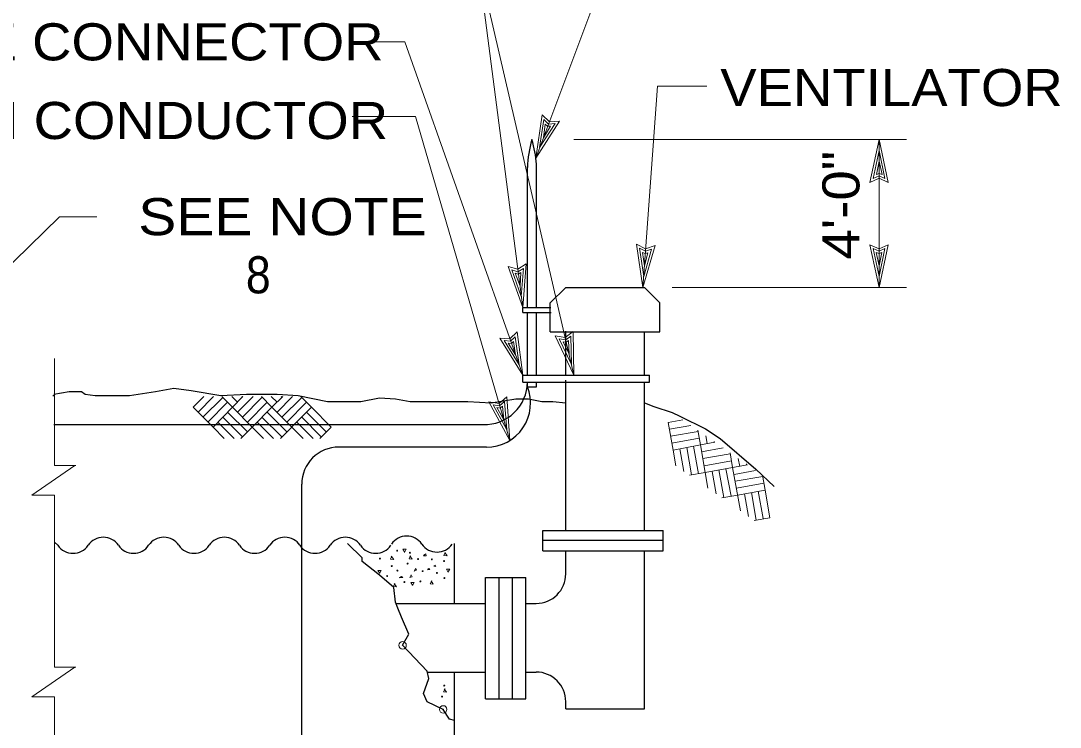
# Model space of a CAD drawing. Extents: x -39.6 to 16.1, y -17.6 to 34.
# Drawn here: x -5.055 to -1.551, y 7.321 to 9.702 of the extents above; entities that cross this region are included whole.
import ezdxf
from ezdxf.enums import TextEntityAlignment as Align

# ---------------------------------------------------------------- set-up
doc = ezdxf.new("R2010")
doc.units = 0
doc.header["$LTSCALE"] = 0.05
doc.header["$PDMODE"] = 32
doc.header["$PDSIZE"] = 0.025
doc.layers.add('1', color=7, linetype='Continuous', lineweight=13)
doc.layers.add('2', color=7, linetype='Continuous', lineweight=13)

msp = doc.modelspace()

# ---------------------------------------------------------------- linework, layer by layer
at = {"layer": '1'}
for p, q in [((-3.11621, 9.77942), (-3.31921, 9.23942)), ((-2.90921, 9.48142), (-2.74321, 9.48142)), ((-3.31921, 9.23942), (-3.29721, 9.38542)), ((-3.31921, 9.23942), (-3.23921, 9.36342)), ((-3.30621, 9.27442), (-3.29221, 9.36942)), ((-3.30621, 9.27442), (-3.25421, 9.35542)), ((-3.29221, 9.36942), (-3.27621, 9.35342)), ((-3.27621, 9.35342), (-3.25421, 9.35542)), ((-3.29321, 9.30742), (-3.28721, 9.35342)), ((-3.29321, 9.30742), (-3.26921, 9.34642)), ((-3.28721, 9.35342), (-3.27921, 9.34642)), ((-3.27921, 9.34642), (-3.26921, 9.34642)), ((-3.19121, 9.30142), (-2.06921, 9.30142)), ((-2.16221, 9.30142), (-2.19321, 9.15742)), ((-2.16221, 8.80342), (-2.16221, 9.30142)), ((-2.16221, 9.30142), (-2.13121, 9.15742)), ((-2.16221, 9.26442), (-2.18221, 9.17042)), ((-2.16221, 9.26442), (-2.14221, 9.17042)), ((-2.16221, 9.22842), (-2.17121, 9.18342)), ((-2.16221, 9.22842), (-2.15221, 9.18342)), ((-2.16221, 9.18742), (-2.17121, 9.18342)), ((-2.15221, 9.18342), (-2.16221, 9.18742)), ((-2.16221, 9.17942), (-2.18221, 9.17042)), ((-2.14221, 9.17042), (-2.16221, 9.17942)), ((-4.92421, 9.04142), (-4.79921, 9.04142)), ((-2.95521, 8.84042), (-2.96921, 8.93542)), ((-2.96921, 8.93542), (-2.94921, 8.92542)), ((-2.95821, 8.80342), (-2.91721, 8.94442)), ((-2.16221, 8.80342), (-2.19321, 8.94742)), ((-2.16221, 8.80342), (-2.13121, 8.94742)), ((-2.95321, 8.87642), (-2.95921, 8.92142)), ((-2.95921, 8.92142), (-2.95021, 8.91742)), ((-2.95521, 8.84042), (-2.92921, 8.93242)), ((-2.95321, 8.87642), (-2.94121, 8.92042)), ((-2.95021, 8.91742), (-2.94121, 8.92042)), ((-2.94921, 8.92542), (-2.92921, 8.93242)), ((-2.16221, 8.84042), (-2.18221, 8.93442)), ((-2.18221, 8.93442), (-2.16221, 8.92542)), ((-2.16221, 8.87642), (-2.17221, 8.92142)), ((-2.17221, 8.92142), (-2.16221, 8.91742)), ((-2.16221, 8.84042), (-2.14221, 8.93442)), ((-2.16221, 8.92542), (-2.14221, 8.93442)), ((-2.16221, 8.87642), (-2.15321, 8.92142)), ((-2.16221, 8.91742), (-2.15321, 8.92142)), ((-3.37921, 8.85642), (-3.36021, 8.86742)), ((-3.36821, 8.77242), (-3.36021, 8.86742)), ((-3.36321, 8.73542), (-3.35121, 8.88242)), ((-3.36821, 8.77242), (-3.40021, 8.86242)), ((-3.40021, 8.86242), (-3.37921, 8.85642)), ((-3.37221, 8.80742), (-3.38821, 8.85142)), ((-3.38821, 8.85142), (-3.37821, 8.84842)), ((-3.37821, 8.84842), (-3.36921, 8.85342)), ((-3.37221, 8.80742), (-3.36921, 8.85342)), ((-2.85921, 8.80342), (-2.06921, 8.80342)), ((-3.19121, 8.50742), (-3.19321, 8.65442)), ((-3.37521, 8.54242), (-3.42621, 8.62442)), ((-3.42621, 8.62442), (-3.40421, 8.62242)), ((-3.40421, 8.62242), (-3.38821, 8.63742)), ((-3.40121, 8.61442), (-3.39421, 8.62142)), ((-3.38721, 8.57642), (-3.39421, 8.62142)), ((-3.37521, 8.54242), (-3.38821, 8.63742)), ((-3.36321, 8.50742), (-3.38221, 8.65342)), ((-3.19121, 8.50742), (-3.25421, 8.64042)), ((-3.19921, 8.54342), (-3.24021, 8.63042)), ((-3.24021, 8.63042), (-3.21821, 8.62642)), ((-3.20721, 8.57842), (-3.22721, 8.62042)), ((-3.22721, 8.62042), (-3.21721, 8.61842)), ((-3.21821, 8.62642), (-3.20121, 8.63942)), ((-3.21721, 8.61842), (-3.20921, 8.62442)), ((-3.20721, 8.57842), (-3.20921, 8.62442)), ((-3.19921, 8.54342), (-3.20121, 8.63942)), ((-3.38721, 8.57642), (-3.41221, 8.61542)), ((-3.41221, 8.61542), (-3.40121, 8.61442)), ((-4.94121, 8.20342), (-4.94121, 8.56342)), ((-4.47421, 8.39942), (-4.43821, 8.43542)), ((-4.45721, 8.38342), (-4.40521, 8.43542)), ((-4.44121, 8.36642), (-4.37421, 8.43242)), ((-4.42421, 8.34942), (-4.35821, 8.41642)), ((-4.34121, 8.39942), (-4.37721, 8.43542)), ((-4.32521, 8.41642), (-4.34421, 8.43542)), ((-4.34121, 8.39942), (-4.30621, 8.43542)), ((-4.34121, 8.39942), (-4.30621, 8.43542)), ((-4.32521, 8.38342), (-4.27221, 8.43542)), ((-4.30821, 8.43242), (-4.31021, 8.43542)), ((-4.30821, 8.36642), (-4.24221, 8.43242)), ((-4.29121, 8.34942), (-4.22521, 8.41642)), ((-4.20921, 8.39942), (-4.24421, 8.43542)), ((-4.19121, 8.41642), (-4.21121, 8.43542)), ((-4.20921, 8.39942), (-4.17221, 8.43542)), ((-4.19121, 8.38342), (-4.13921, 8.43542)), ((-4.17521, 8.43242), (-4.17721, 8.43542)), ((-4.17521, 8.36642), (-4.10821, 8.43242)), ((-4.15821, 8.34942), (-4.09221, 8.41642)), ((-4.07521, 8.39942), (-4.11121, 8.43542)), ((-3.44121, 8.40442), (-3.42421, 8.41842)), ((-3.41721, 8.32342), (-3.42421, 8.41842)), ((-3.40721, 8.28742), (-3.41721, 8.43442)), ((-4.40721, 8.33242), (-4.34121, 8.39942)), ((-4.29121, 8.31642), (-4.35821, 8.38342)), ((-4.27521, 8.33242), (-4.34121, 8.39942)), ((-4.27521, 8.33242), (-4.20921, 8.39942)), ((-4.15821, 8.31642), (-4.22521, 8.38342)), ((-4.14221, 8.33242), (-4.07521, 8.39942)), ((-4.02621, 8.31642), (-4.09221, 8.38342)), ((-4.00921, 8.33242), (-4.07521, 8.39942)), ((-3.41721, 8.32342), (-3.46321, 8.40742)), ((-3.46321, 8.40742), (-3.44121, 8.40442)), ((-3.42721, 8.35742), (-3.45021, 8.39842)), ((-3.45021, 8.39842), (-3.43921, 8.39642)), ((-3.43921, 8.39642), (-3.43121, 8.40342)), ((-3.42721, 8.35742), (-3.43121, 8.40342)), ((-4.33621, 8.29442), (-4.39121, 8.34942)), ((-4.30821, 8.29942), (-4.37421, 8.36642)), ((-4.20321, 8.29442), (-4.25821, 8.34942)), ((-4.17521, 8.29942), (-4.24221, 8.36642)), ((-4.07021, 8.29442), (-4.12521, 8.34942)), ((-4.04221, 8.29942), (-4.10821, 8.36642)), ((-2.87321, 8.34842), (-2.82321, 8.35742)), ((-4.31321, 8.29442), (-4.27521, 8.33242)), ((-4.23721, 8.29442), (-4.27521, 8.33242)), ((-4.18021, 8.29442), (-4.14121, 8.33242)), ((-4.04721, 8.29442), (-4.00921, 8.33242)), ((-2.86821, 8.32542), (-2.79621, 8.33842)), ((-2.86521, 8.30242), (-2.77221, 8.31842)), ((-2.76421, 8.27242), (-2.77321, 8.32242)), ((-2.86121, 8.27842), (-2.76821, 8.29542)), ((-2.85621, 8.25442), (-2.76421, 8.27242)), ((-2.76421, 8.27242), (-2.71521, 8.28142)), ((-2.76421, 8.27242), (-2.71521, 8.28142)), ((-2.74821, 8.17942), (-2.76421, 8.27242)), ((-2.74121, 8.27742), (-2.74621, 8.30342)), ((-2.71821, 8.28042), (-2.71821, 8.28442)), ((-2.82021, 8.18342), (-2.83421, 8.25942)), ((-2.79421, 8.17142), (-2.81021, 8.26342)), ((-2.77021, 8.17542), (-2.78721, 8.26842)), ((-2.76021, 8.24942), (-2.68721, 8.26242)), ((-2.75621, 8.22642), (-2.66421, 8.24242)), ((-2.65621, 8.19642), (-2.66421, 8.24642)), ((-5.01821, 8.10342), (-4.87321, 8.20342)), ((-4.94121, 8.20342), (-4.86921, 8.20342)), ((-2.75221, 8.20242), (-2.65921, 8.21942)), ((-2.65621, 8.19642), (-2.60521, 8.20542)), ((-2.63121, 8.20042), (-2.63721, 8.22742)), ((-2.60921, 8.20442), (-2.60921, 8.20842)), ((-2.80121, 8.17042), (-2.74821, 8.17942)), ((-2.74821, 8.17942), (-2.65621, 8.19642)), ((-2.73921, 8.12642), (-2.74821, 8.17942)), ((-2.71121, 8.10742), (-2.72421, 8.18342)), ((-2.68521, 8.09542), (-2.70221, 8.18842)), ((-2.66121, 8.09942), (-2.67821, 8.19242)), ((-2.65021, 8.17342), (-2.57821, 8.18642)), ((-2.64721, 8.15042), (-2.55421, 8.16642)), ((-2.54621, 8.12042), (-2.55521, 8.17042)), ((-2.64221, 8.12642), (-2.55021, 8.14342)), ((-5.01821, 8.10342), (-4.94121, 8.10342)), ((-4.94121, 7.52342), (-4.94121, 8.10342)), ((-2.69221, 8.09442), (-2.63821, 8.10342)), ((-2.63921, 8.10342), (-2.54621, 8.12042)), ((-2.60221, 8.03142), (-2.61521, 8.10742)), ((-2.57621, 8.01942), (-2.59221, 8.11242)), ((-2.55321, 8.02442), (-2.56921, 8.11642)), ((-2.53021, 8.02742), (-2.54621, 8.12042)), ((-2.58321, 8.01842), (-2.53021, 8.02742)), ((-5.01821, 7.42342), (-4.87321, 7.52342)), ((-4.94121, 7.52342), (-4.86921, 7.52342)), ((-5.01821, 7.42342), (-4.94121, 7.42342)), ((-4.94121, 7.18642), (-4.94121, 7.42342))]:
    msp.add_line(p, q, dxfattribs=at)
at = {"layer": '1', "lineweight": 25}
for p, q in [((-3.31721, 8.73542), (-3.31721, 9.21842)), ((-3.34721, 8.73542), (-3.34721, 9.21142)), ((-3.27021, 8.75142), (-3.21821, 8.80342)), ((-3.21821, 8.80342), (-2.95321, 8.80342)), ((-2.90121, 8.75142), (-2.95321, 8.80342)), ((-3.36321, 8.73542), (-3.26821, 8.73542)), ((-3.36321, 8.71842), (-3.36321, 8.73542)), ((-3.27021, 8.65342), (-3.27021, 8.75142)), ((-2.90121, 8.65342), (-2.90121, 8.75142)), ((-3.36321, 8.71842), (-3.26721, 8.71842)), ((-3.34721, 8.50742), (-3.34721, 8.71842)), ((-3.31721, 8.50742), (-3.31721, 8.71842)), ((-3.21821, 8.50742), (-3.21821, 8.65542)), ((-3.27021, 8.65342), (-2.90121, 8.65342)), ((-2.95321, 8.50742), (-2.95321, 8.65142)), ((-3.36321, 8.50742), (-2.93621, 8.50742)), ((-3.36321, 8.48442), (-3.36321, 8.50742)), ((-3.36321, 8.48442), (-2.93621, 8.48442)), ((-3.34721, 8.46842), (-3.34721, 8.48442)), ((-3.31721, 8.46842), (-3.31721, 8.48442)), ((-3.21821, 8.46842), (-3.21821, 8.49042)), ((-2.95321, 8.46242), (-2.95321, 8.48442)), ((-2.93621, 8.48442), (-2.93621, 8.50742)), ((-3.34721, 8.46842), (-3.31721, 8.46842)), ((-3.21821, 8.38142), (-3.21821, 8.46842)), ((-2.95321, 8.32642), (-2.95321, 8.46242)), ((-4.94721, 8.43942), (-4.94121, 8.43942)), ((-3.21821, 7.98442), (-3.21821, 8.38142)), ((-4.94421, 8.34142), (-3.49621, 8.34142)), ((-2.95321, 7.98442), (-2.95321, 8.32642)), ((-3.48521, 8.26542), (-3.98321, 8.26542)), ((-4.10821, 7.20742), (-4.10821, 8.14042)), ((-3.29521, 7.98442), (-2.89021, 7.98442)), ((-3.29521, 7.91542), (-3.29521, 7.98442)), ((-2.89021, 7.91542), (-2.89021, 7.98442)), ((-4.93021, 7.93442), (-4.94121, 7.94442)), ((-3.59321, 7.73842), (-3.59321, 7.94042)), ((-3.29521, 7.95142), (-2.89021, 7.95142)), ((-3.29521, 7.91542), (-2.89021, 7.91542)), ((-3.21821, 7.83842), (-3.21821, 7.91542)), ((-2.95321, 7.38342), (-2.95321, 7.91542)), ((-3.48821, 7.41742), (-3.48821, 7.82542)), ((-3.48821, 7.82542), (-3.35321, 7.82542)), ((-3.44221, 7.41742), (-3.44221, 7.82542)), ((-3.39821, 7.41742), (-3.39821, 7.82542)), ((-3.35321, 7.41742), (-3.35321, 7.82542)), ((-3.78821, 7.73842), (-3.48921, 7.73842)), ((-3.35321, 7.73842), (-3.31821, 7.73842)), ((-3.68521, 7.50742), (-3.48921, 7.50742)), ((-3.59321, 7.20842), (-3.59321, 7.50542)), ((-3.35221, 7.50742), (-3.31821, 7.50742)), ((-3.48821, 7.41742), (-3.35321, 7.41742)), ((-3.21821, 7.38342), (-3.21821, 7.40742)), ((-3.21821, 7.38342), (-2.95321, 7.38342))]:
    msp.add_line(p, q, dxfattribs=at)
at = {"layer": '1'}
for points in [[(-3.66321, 9.90442), (-3.51421, 9.90442), (-3.19121, 8.50742)], [(-3.51421, 9.90442), (-3.36321, 8.73542), (-3.41221, 8.87442)], [(-3.90421, 9.63042), (-3.76121, 9.63042), (-3.36321, 8.50742), (-3.44021, 8.63242)], [(-2.90921, 9.48142), (-2.95821, 8.80342), (-2.97921, 8.94942)], [(-3.93821, 9.37942), (-3.72421, 9.37942), (-3.40721, 8.28742), (-3.47721, 8.41742)], [(-3.29721, 9.38542), (-3.27321, 9.36142), (-3.23921, 9.36342)], [(-2.13121, 9.15742), (-2.16221, 9.17142), (-2.19321, 9.15742)], [(-4.92421, 9.04142), (-5.33321, 8.64242), (-5.25221, 8.76542)], [(-2.97921, 8.94942), (-2.94921, 8.93342), (-2.91721, 8.94442)], [(-2.19321, 8.94742), (-2.16221, 8.93342), (-2.13121, 8.94742)], [(-3.41221, 8.87442), (-3.38021, 8.86442), (-3.35121, 8.88242)], [(-3.25421, 8.64042), (-3.22021, 8.63442), (-3.19321, 8.65442)], [(-3.44021, 8.63242), (-3.40621, 8.63042), (-3.38221, 8.65342)], [(-4.10321, 8.29442), (-4.20921, 8.39942), (-4.17221, 8.43542)], [(-3.47721, 8.41742), (-3.44321, 8.41242), (-3.41721, 8.43442)], [(-4.36921, 8.29442), (-4.40721, 8.33242), (-4.47421, 8.39942)], [(-2.84721, 8.20242), (-2.85621, 8.25442), (-2.87321, 8.34842)], [(-2.62921, 8.05042), (-2.65621, 8.19642), (-2.60521, 8.20542)]]:
    msp.add_lwpolyline(points, dxfattribs=at)
at = {"layer": '1', "lineweight": 25}
for points in [[(-4.94421, 8.44342), (-4.89221, 8.45242), (-4.85021, 8.45242), (-4.83821, 8.44342), (-4.80421, 8.43942), (-4.68821, 8.43942), (-4.60121, 8.45242), (-4.53921, 8.46442), (-4.48121, 8.45642), (-4.38121, 8.43942), (-4.29421, 8.44342), (-4.19121, 8.44342), (-4.12021, 8.43942), (-4.02121, 8.41842), (-3.90921, 8.41842), (-3.84621, 8.43142), (-3.79221, 8.42742), (-3.74321, 8.41842), (-3.66021, 8.41842), (-3.54821, 8.41842), (-3.46921, 8.41442), (-3.38621, 8.42742), (-3.34421, 8.42742), (-3.29921, 8.41842), (-3.26221, 8.41842), (-3.21821, 8.41442)], [(-2.95321, 8.41442), (-2.92121, 8.40242), (-2.85921, 8.38142), (-2.83421, 8.36942), (-2.74721, 8.32742), (-2.69721, 8.29442), (-2.57721, 8.19042), (-2.51521, 8.13242)], [(-3.76821, 7.59742), (-3.74721, 7.63442), (-3.77221, 7.69242), (-3.78421, 7.72242), (-3.79221, 7.74242), (-3.79721, 7.79242), (-3.84621, 7.83342), (-3.90421, 7.87942), (-3.90421, 7.89242), (-3.95421, 7.94042)], [(-3.63121, 7.38142), (-3.68521, 7.40642), (-3.69721, 7.43542), (-3.68021, 7.48542), (-3.68521, 7.51042), (-3.76821, 7.59742)], [(-3.59321, 7.34442), (-3.61021, 7.34842), (-3.63121, 7.38142)]]:
    msp.add_lwpolyline(points, dxfattribs=at)
for centre, radius, start, end in [((-3.0014, 9.20043), 0.34588, 163.02419, 178.84281), ((-3.70426, 9.19132), 0.388, 4.00419, 16.48399), ((-3.49172, 8.48587), 0.14452, 268.22155, 359.42416), ((-3.48538, 8.41362), 0.14864, 270.06569, 21.63276), ((-3.98321, 8.14042), 0.125, 90, 180), ((-4.77721, 7.89992), 0.06157, 34.0772, 145.92281), ((-4.57321, 7.89992), 0.06157, 34.0772, 145.92281), ((-4.36921, 7.89992), 0.06157, 34.0772, 145.92281), ((-4.16521, 7.89992), 0.06157, 34.0772, 145.92281), ((-3.96121, 7.89992), 0.06157, 34.0772, 145.92281), ((-3.75421, 7.90392), 0.06157, 34.0772, 145.92281), ((-4.87921, 7.96892), 0.06157, 214.0772, 325.92281), ((-4.67521, 7.96892), 0.06157, 214.0772, 325.92281), ((-4.47121, 7.96892), 0.06157, 214.0772, 325.92281), ((-4.26721, 7.96892), 0.06157, 214.0772, 325.92281), ((-4.06321, 7.96892), 0.06157, 214.0772, 325.92281), ((-3.85921, 7.96892), 0.06157, 214.0772, 325.92281), ((-3.65221, 7.97292), 0.06157, 214.0772, 325.92281), ((-3.31821, 7.83842), 0.1, 270, 0), ((-3.31821, 7.40742), 0.1, 0, 90)]:
    msp.add_arc(centre, radius, start, end, dxfattribs=at)
at = {"layer": '1'}
for p in [(-3.76821, 7.59742), (-3.63121, 7.38142)]:
    msp.add_point(p, dxfattribs=at)
at = {"layer": '2'}
msp.add_line((-3.69721, 7.90042), (-3.69021, 7.90542), dxfattribs=at)
for points in [[(-3.76221, 7.91242), (-3.76721, 7.92142), (-3.75621, 7.92142), (-3.76221, 7.91042)], [(-3.80421, 7.89742), (-3.80921, 7.88742), (-3.79821, 7.88642), (-3.80621, 7.89742)], [(-3.74121, 7.89842), (-3.74621, 7.88842), (-3.73621, 7.88742), (-3.74421, 7.89842)], [(-3.69021, 7.90542), (-3.68921, 7.89842), (-3.69721, 7.89842)], [(-3.62421, 7.91042), (-3.62921, 7.90042), (-3.61821, 7.89942), (-3.62621, 7.91042)], [(-3.84621, 7.84142), (-3.85121, 7.84942), (-3.84021, 7.84942), (-3.84621, 7.83942)], [(-3.68421, 7.85242), (-3.68021, 7.85642), (-3.67621, 7.85242), (-3.68321, 7.85142)], [(-3.66321, 7.86542), (-3.65821, 7.86742), (-3.65621, 7.86242), (-3.66321, 7.86442)], [(-3.61521, 7.84542), (-3.62021, 7.85342), (-3.60921, 7.85342), (-3.61521, 7.84342)], [(-3.77721, 7.82642), (-3.77221, 7.82942), (-3.76721, 7.82642), (-3.77921, 7.82442)], [(-3.67021, 7.81442), (-3.67521, 7.80442), (-3.66521, 7.80342), (-3.67221, 7.81442)], [(-3.79421, 7.80542), (-3.79921, 7.79542), (-3.78821, 7.79442), (-3.79621, 7.80542)], [(-3.73521, 7.80042), (-3.74021, 7.80942), (-3.72921, 7.80942), (-3.73521, 7.79942)], [(-3.62521, 7.45042), (-3.63021, 7.44042), (-3.62021, 7.43942), (-3.62821, 7.45042)]]:
    msp.add_lwpolyline(points, dxfattribs=at)
for points in [[(-3.72921, 7.84742), (-3.72421, 7.85642), (-3.72121, 7.85042)], [(-3.74421, 7.82642), (-3.73921, 7.83442), (-3.73621, 7.82842)]]:
    msp.add_lwpolyline(points, close=True, dxfattribs=at)
for centre in [(-3.84471, 7.88954), (-3.78646, 7.91629), (-3.74371, 7.90954), (-3.71596, 7.88779), (-3.66971, 7.88679), (-3.80496, 7.86429), (-3.78571, 7.84904), (-3.75121, 7.87254), (-3.70071, 7.84729), (-3.62846, 7.88104), (-3.82021, 7.83054), (-3.70821, 7.81279), (-3.65271, 7.84154), (-3.62746, 7.82379), (-3.76221, 7.81029), (-3.62771, 7.46154), (-3.63521, 7.42454)]:
    msp.add_circle(centre, 0.00162, dxfattribs=at)

# ---------------------------------------------------------------- texts
at = {"layer": '1'}
for s, width, p in [('CABLE CONNECTOR', 1.1, (-5.67121, 9.56842)), ('DOWN CONDUCTOR', 1.1, (-5.64521, 9.30342)), ('SEE NOTE', 1.15, (-4.65921, 8.97942))]:
    msp.add_text(s, height=0.125, dxfattribs=dict(at, width=width)).set_placement(p)
for s, width, p in [('VENTILATOR', 1.1, (-2.12021, 9.41442)), ('8', 0.9, (-4.25471, 8.78342))]:
    msp.add_text(s, height=0.125, dxfattribs=dict(at, width=width)).set_placement(p, align=Align.CENTER)
at = {"layer": '1', "width": 1.1}
msp.add_text('4\'-0"', height=0.125, rotation=90, dxfattribs=at).set_placement((-2.22821, 9.08042), align=Align.CENTER)

doc.saveas('drawing.dxf')
